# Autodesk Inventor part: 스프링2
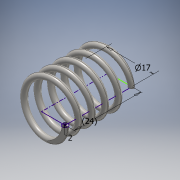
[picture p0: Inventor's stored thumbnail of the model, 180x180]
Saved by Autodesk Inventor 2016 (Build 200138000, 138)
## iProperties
Created: 2019-11
Part Number: 스프링2
Material: 스테인레스 스틸
Document SubType Name: Modeling
Designer: user
Mass: 6.55763 g
Surface Area: 16.7052 cm^2
Volume: 0.819704 cm^3
Density: 8 g/cm^3
Appearance: 반연마
Author: user
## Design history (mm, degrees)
sketch "스케치1"
  geometry: L1 (0, 0)-(8.5, 0); L2 (8.5, 0)-(8.5, 17.5); L3 (8.5, 17.5)-(0, 17.5); L4 (0, 17.5)-(0, 0); C1 r 1 at (8.5, 0)
  constraints: 8 end point, 2 parallel, 1 centre point, 1 coincident, 1 horizontal, 1 perpendicular
  dimensions: "d0" = 17.5 distance between parallel lines of L1 L3 (derived); "d1" = 17 diameter of L2 L4; "d2" = 2 diameter of C1
feature "코일1" sketch "스케치1" pitch "d3" = 10; turns "d5" = 5; dims "d4" = 17.5 (= d0), "d6" = 0, angle "d7" = 90 deg, angle "d8" = 90 deg, "d9" = 0, "d10" = 0
sketch "스케치2"
  geometry: L1 (0, 14.377)-(17.5, 14.377); L2 (17.5, 14.377)-(17.5, -14.377); L3 (17.5, -14.377)-(0, -14.377); L4 (0, -14.377)-(0, 14.377); 2 further points
  constraints: 8 end point, 2 parallel, 1 coincident, 1 horizontal, 1 midpoint, 1 perpendicular
  dimensions: "d11" = 28.75382 distance of L1.end L2.end; "d12" = 17.5 distance between parallel lines of L4 L2 (= d0)
extrude "돌출1" sketch "스케치2" stored distance "d13" = 26.25; taper "d14" = 0 deg
node "솔리드1"
